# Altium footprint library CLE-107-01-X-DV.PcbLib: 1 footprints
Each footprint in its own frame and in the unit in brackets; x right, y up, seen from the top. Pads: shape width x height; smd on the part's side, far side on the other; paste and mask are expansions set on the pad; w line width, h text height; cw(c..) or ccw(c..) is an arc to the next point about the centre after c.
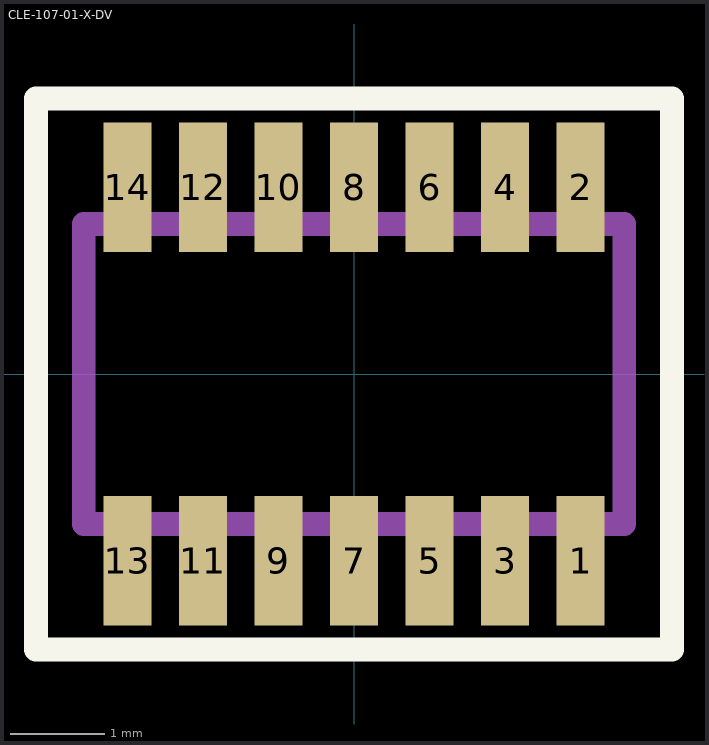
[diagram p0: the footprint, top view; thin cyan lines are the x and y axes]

## CLE-107-01-X-DV [mil]
pads (14):
  rect 20x54 smd mask+2: 1(94.5,-78) 2(94.5,78) 3(63,-78) 4(63,78) 5(31.5,-78) 6(31.5,78) 7(0,-78) 8(0,78) 9(-31.5,-78) 10(-31.5,78) 11(-63,-78) 12(-63,78) 13(-94.5,-78) 14(-94.5,78)
Top Overlay:
  lines w10: -132.75,-115 132.75,-115 132.75,115 -132.75,115 -132.75,-115
Mechanical 1:
  lines w10: -112.75,-62.5 112.75,-62.5 112.75,62.5 -112.75,62.5 -112.75,-62.5
  text "J1" at -17.3,-17.72 h29.53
